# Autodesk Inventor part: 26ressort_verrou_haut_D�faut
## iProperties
Created: 2011-01
Part Number: 26ressort_verrou_haut_D�faut
Document SubType Name: Modeling
Designer: eric
Density: 1 g/cm^3
Mass: 0.756418 g
Surface Area: 16.7077 cm^2
Volume: 0.756418 cm^3
Author: eric
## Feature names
1. Base1
